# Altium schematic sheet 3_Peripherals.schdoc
size 309 x 223 mm; Symbol: Sheet-Symbol_A4; Device: Sheet-Symbol_A4; @Project Name: Digital_Watch_V01; @Page Count: 3; @Update Date: 2024-09-21; @Create Date: 2024-09-08; @Schematic Name: D-Watch_Sch; @Page No: 3; @Page Name: Peripherals; Company: EasyEDA.com; Reviewed: EasyEDA; Version: V0.1; Page Size: A4; Part Number: JLCPCB-002; Drawn: EasyEDA; @Board Name: D-Watch_Board; @Create Time: 14:32:57; @Update Time: 15:39:19
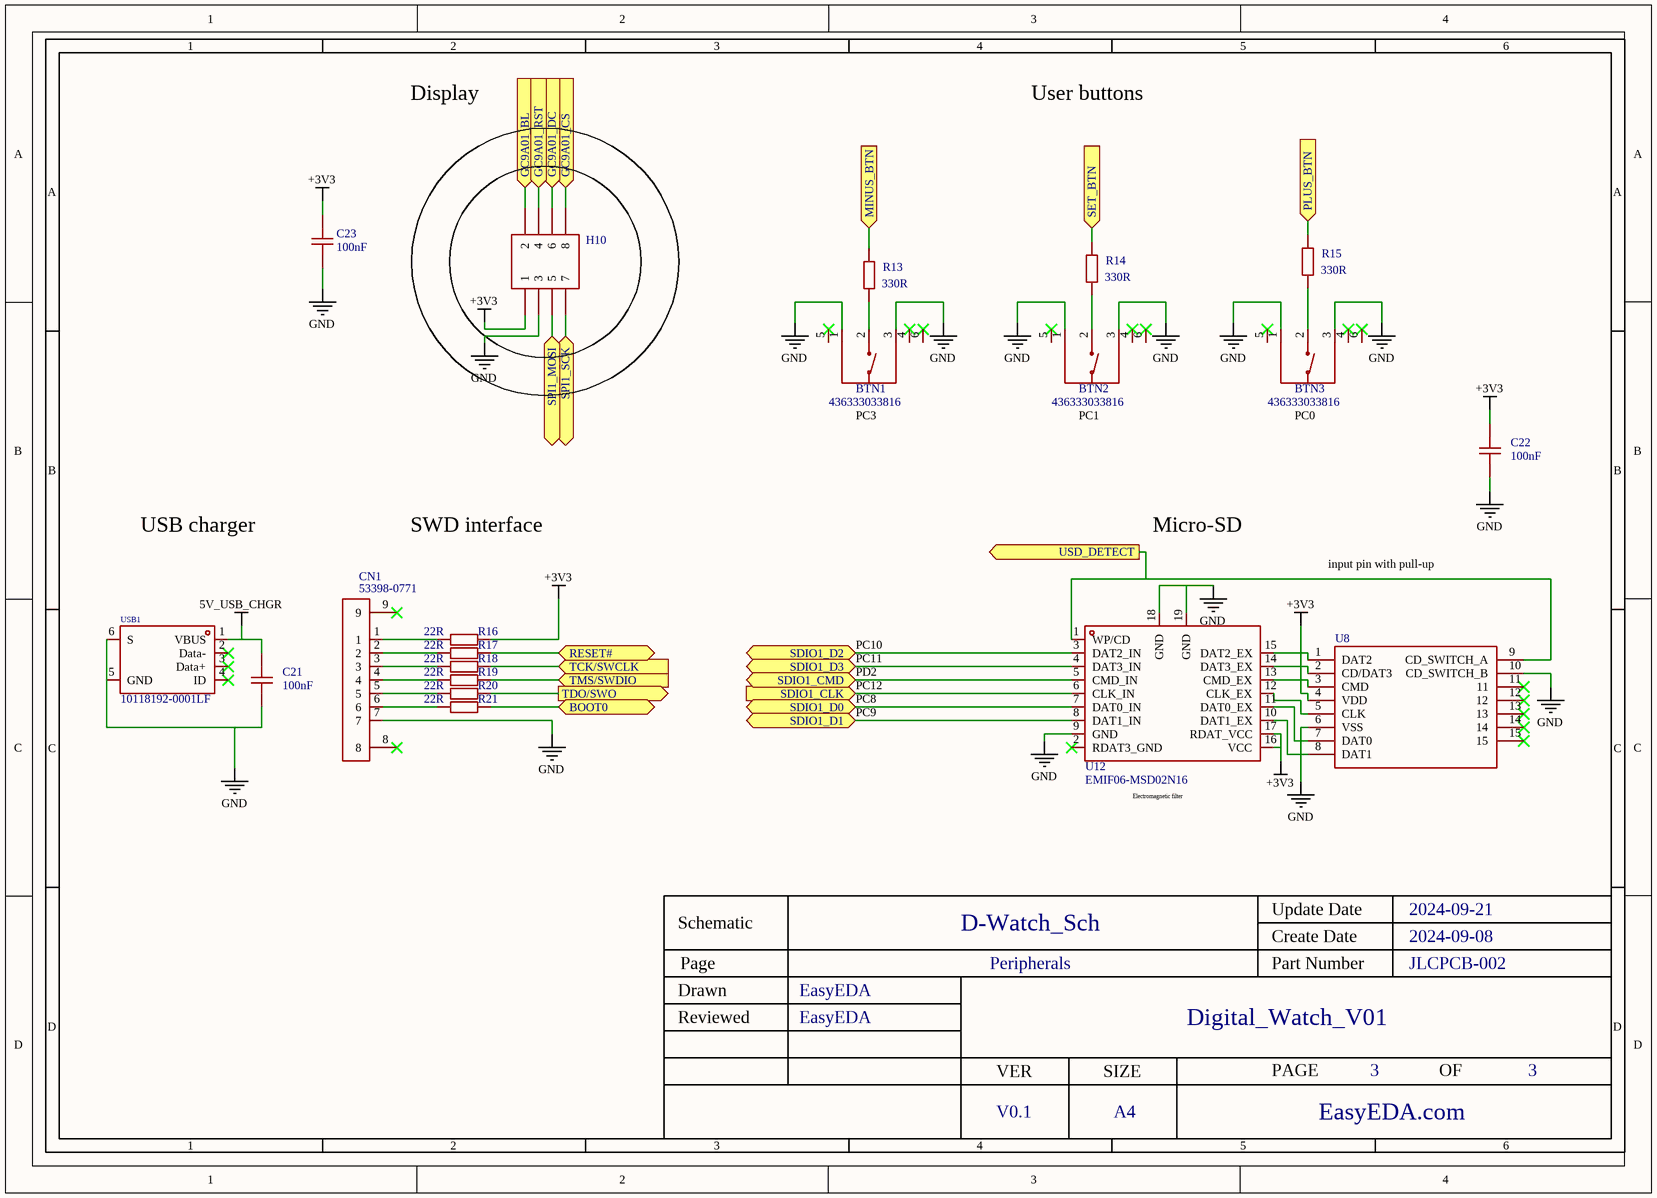
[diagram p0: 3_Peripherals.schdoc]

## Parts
BTN1  436333033816  [SW-SMD_436333033816]  (value not drawn)
BTN2  436333033816  [SW-SMD_436333033816]  (value not drawn)
BTN3  436333033816  [SW-SMD_436333033816]  (value not drawn)
C21  100nF  [C0603]  (value not drawn)
C22  100nF  [C0603]  (value not drawn)
C23  100nF  [C0603]  (value not drawn)
CN1  53398-0771  [CONN-SMD_7P-P1.25_53398-0771]  (value not drawn)
H10  HDR-F-2.54_2x4  [HDR-TH_8P-P2.54-V-F-R2-C4-S2.54-1]  (value not drawn)
R13  330R  [R0603]  (value not drawn)
R14  330R  [R0603]  (value not drawn)
R15  330R  [R0603]  (value not drawn)
R16  22R  [R0603]  (value not drawn)
R17  22R  [R0603]  (value not drawn)
R18  22R  [R0603]  (value not drawn)
R19  22R  [R0603]  (value not drawn)
R20  22R  [R0603]  (value not drawn)
R21  22R  [R0603]  (value not drawn)
U8  DM3BT-DSF-PEJS_  [DM3BTDSFPEJS]  (value not drawn)
U12  EMIF06-MSD02N16  [QFN-16L_L3.5-W1.2-P0.40_EMIF06-MSD02N16]  (value not drawn)
USB1  10118192-0001LF  [MICRO-USB-SMD_10118192-0001LF_1]  (value not drawn)

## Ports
BOOT0 (bidir), GC9A01_BL (in), GC9A01_CS (in), GC9A01_DC (in), GC9A01_RST (in), MINUS_BTN (in), PLUS_BTN (in), RESET# (bidir), SDIO1_CLK (in), SDIO1_CMD (bidir), SDIO1_D0 (bidir), SDIO1_D1 (bidir), SDIO1_D2 (bidir), SDIO1_D3 (bidir), SET_BTN (in), SPI1_MOSI (bidir), SPI1_SCK (bidir), TCK/SWCLK (in), TDO/SWO (out), TMS/SWDIO (in), USD_DETECT (out)

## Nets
5V_USB_CHGR: C21.1 USB1.1(VBUS)
+3V3: C22.1 C23.1 H10.1 R16.1 U8.4(VDD) U12.16(VCC) U12.17(RDAT_VCC)
GND: BTN1.1 BTN1.3 BTN2.1 BTN2.3 BTN3.1 BTN3.3 C21.2 C22.2 C23.2 CN1.7 H10.3 U8.6(VSS) U8.10(CD_SWITCH_B) U12.9(GND) U12.18(GND) U12.19(GND) USB1.5(GND) USB1.6(S)
BOOT0: R21.1 ; port BOOT0
GC9A01_BL: H10.2 ; port GC9A01_BL
GC9A01_CS: H10.8 ; port GC9A01_CS
GC9A01_DC: H10.6 ; port GC9A01_DC
GC9A01_RST: H10.4 ; port GC9A01_RST
MINUS_BTN: R13.2 ; port MINUS_BTN
PLUS_BTN: R15.2 ; port PLUS_BTN
RESET#: R17.1 ; port RESET#
SDIO1_CLK: U12.6(CLK_IN) ; port SDIO1_CLK
SDIO1_CMD: U12.5(CMD_IN) ; port SDIO1_CMD
SDIO1_D0: U12.7(DAT0_IN) ; port SDIO1_D0
SDIO1_D1: U12.8(DAT1_IN) ; port SDIO1_D1
SDIO1_D2: U12.3(DAT2_IN) ; port SDIO1_D2
SDIO1_D3: U12.4(DAT3_IN) ; port SDIO1_D3
SET_BTN: R14.2 ; port SET_BTN
SPI1_MOSI: H10.5 ; port SPI1_MOSI
SPI1_SCK: H10.7 ; port SPI1_SCK
TCK/SWCLK: R18.1 ; port TCK/SWCLK
TDO/SWO: R20.1 ; port TDO/SWO
TMS/SWDIO: R19.1 ; port TMS/SWDIO
USD_DETECT: U8.9(CD_SWITCH_A) U12.1(WP/CD) ; port USD_DETECT
NetBTN1_2: BTN1.2 R13.1
NetBTN2_2: BTN2.2 R14.1
NetBTN3_2: BTN3.2 R15.1
NetCN1_1: CN1.1 R16.2
NetCN1_2: CN1.2 R17.2
NetCN1_3: CN1.3 R18.2
NetCN1_4: CN1.4 R19.2
NetCN1_5: CN1.5 R20.2
NetCN1_6: CN1.6 R21.2
NetU8_1: U8.1(DAT2) U12.15(DAT2_EX)
NetU8_2: U8.2(CD/DAT3) U12.14(DAT3_EX)
NetU8_3: U8.3(CMD) U12.13(CMD_EX)
NetU8_5: U8.5(CLK) U12.12(CLK_EX)
NetU8_7: U8.7(DAT0) U12.11(DAT0_EX)
NetU8_8: U8.8(DAT1) U12.10(DAT1_EX)

Not connected (* = marked no-connect by the designer): BTN1 4* 5* 6*; BTN2 4* 5* 6*; BTN3 4* 5* 6*; CN1 8* 9*; U8 11* 12* 13* 14* 15*; U12 2(RDAT3_GND)*; USB1 2(Data-)* 3(Data+)* 4(ID)*

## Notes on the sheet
- Display
- User buttons
- PC3
- PC1
- PC0
- USB charger
- SWD interface
- Micro-SD
- input pin with pull-up
- PC10
- PC11
- PD2
- PC8
- PC9
- PC12
- (near U12) Electromagnetic filter

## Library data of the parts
BTN1-BTN3 = 436333033816: Circuit:SPST - normally open Actuator Style:Round Button Operating Force:160gf Mounting Style:Standing paste Contact Current:50mA Voltage Rating (DC):12V Pin Style:SMDSplicing Operating Temperature:-40℃~+85℃ Operating Temperature:-40℃~+85℃; Manufacturer: Wurth(伍尔特); Add into BOM: yes; Operating Force: 160gf; Contact Current: 50mA; Voltage Rating (DC): 12V
C21-C23 = GCJ188R71C104KA01D: Capacitance: Tolerance:±10% Tolerance:±10% Voltage Rated: Temperature Coefficient:; Manufacturer: muRata(村田); Add into BOM: yes; Tolerance: ±10%
CN1 = 53398-0771: Manufacturer: MOLEX; Manufacturer Part: 533980771; Convert to PCB: yes
H10 = HDR-F-2.54_2x4: Add into BOM: yes
R13-R21 = Res_0603: Symbol: Res; Convert to PCB: yes
U8 = DM3BT-DSF-PEJS_: Add into BOM: yes
U12 = EMIF06-MSD02N16: Manufacturer: ST(意法半导体); Add into BOM: yes
USB1 = 10118192-0001LF: Connector Type:Micro-B Standard:USB 2.0 Gender:Female Number of Ports:1 Number of Contacts:5P Mounting Style:卧贴 Current Rating - Power (Max):- Operating Temperature Range:-30℃~+80℃ Operating Temperature Range:-30℃~+80℃; Manufacturer: Amphenol; Add into BOM: yes; Gender: Female; Number of Ports: 1; Number of Contacts: 5P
